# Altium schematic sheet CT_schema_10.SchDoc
size 146 x 119 mm
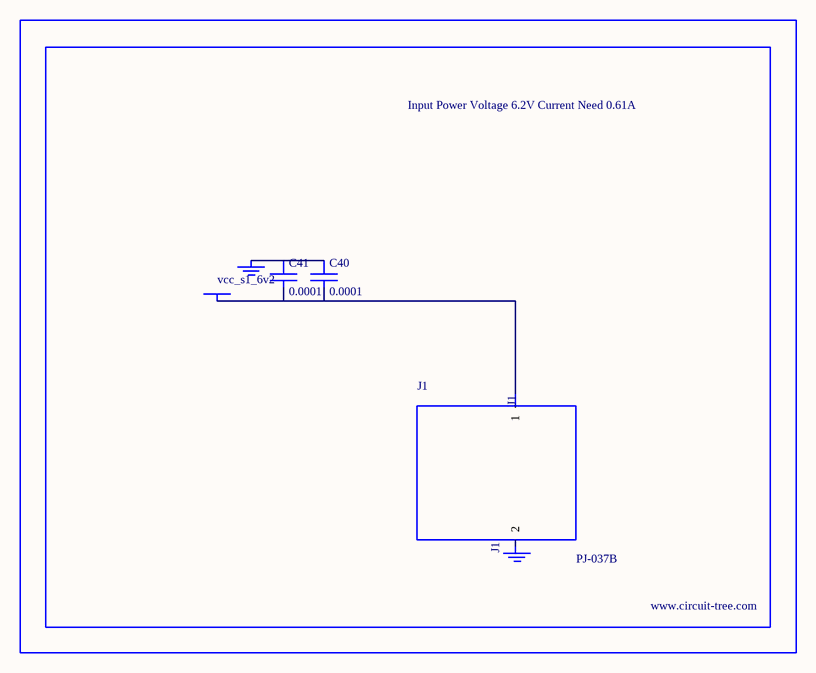
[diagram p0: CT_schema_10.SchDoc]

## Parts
BORDER9  (no value)
C40  0.0001  [EXV-9H]
C41  0.0001  [EXV-9H]
GND_INSTANCE_9_0  (no value)
GND_INSTANCE_9_1  (no value)
J1  PJ-037B  [PJ-037B_PACKAGE]
POWER_INSTANCE_9_0  vcc_s1_6v2

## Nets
NetC40_1: C40.1 C41.1 GND_INSTANCE_9_0.0(GND)
NetC40_2: C40.2 C41.2 J1.1 POWER_INSTANCE_9_0.0(PWR)

Not connected (* = marked no-connect by the designer): GND_INSTANCE_9_1 0(GND); J1 2

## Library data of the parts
BORDER9 = BORDER_PAGE9
C40 C41 = EDK107M035A9HAA
GND_INSTANCE_9_0 GND_INSTANCE_9_1 = GND
POWER_INSTANCE_9_0 = PWR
